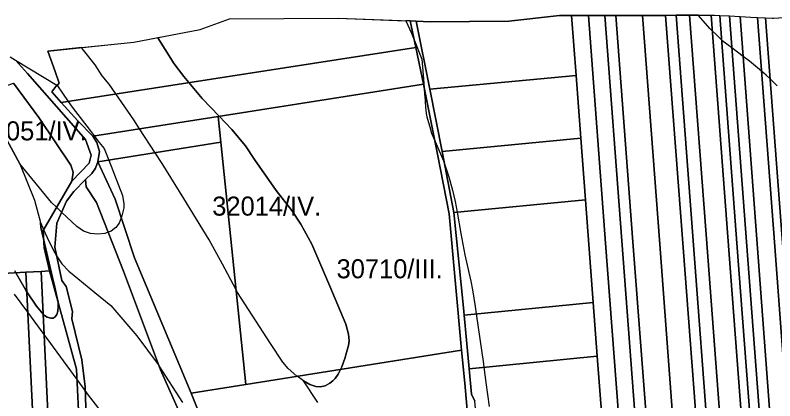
# Model space of a CAD drawing. Extents: x -521939 to -516426, y -1197857 to -1189551.
# Drawn here: x -519736 to -519138, y -1190305 to -1190001 of the extents above; entities that cross this region are included whole.
import ezdxf

# ---------------------------------------------------------------- set-up
doc = ezdxf.new("R2010")
doc.units = 0
for name, color, linetype in [('95560013', 7, 'Continuous'), ('95630013', 7, 'Continuous'), ('95640013', 7, 'Continuous'), ('95660013', 7, 'Continuous')]:
    doc.layers.add(name, color=color, linetype=linetype)

msp = doc.modelspace()

# ---------------------------------------------------------------- linework, layer by layer
at = {"layer": '95560013'}
for points in [[(-519481.8, -1190003.43), (-519425.02, -1190005.62), (-519420.54, -1190026.44), (-519524.15, -1190042.53), (-519700.01, -1190069.84), (-519707.58, -1190061.41), (-519703.4, -1190056.13), (-519701.77, -1190054.51), (-519704.94, -1190045.39), (-519710.52, -1190029.36), (-519655.77, -1190023.65), (-519642.78, -1190022.29), (-519590.6, -1190012.36), (-519567.31, -1190003.84)], [(-519347.33, -1190005.8), (-519307.47, -1190001.42), (-519297.85, -1190001.39), (-519294.3, -1190048.49), (-519409.64, -1190059.44), (-519420.4, -1190005.8), (-519409.39, -1190006.22)], [(-519286.91, -1190146.52), (-519290.57, -1190097.95), (-519294.3, -1190048.49), (-519297.85, -1190001.39), (-519284.59, -1190001.35), (-519271.04, -1190180.87), (-519257.49, -1190360.49), (-519243.94, -1190540.06), (-519241.8, -1190568.42), (-519254.99, -1190569.86), (-519260.41, -1190497.97), (-519273.79, -1190320.5), (-519277.61, -1190269.89), (-519280.81, -1190227.48)], [(-519271.58, -1190001.31), (-519258.19, -1190178.89), (-519244.8, -1190356.47), (-519231.41, -1190534.05), (-519228.93, -1190566.94), (-519241.8, -1190568.42), (-519243.94, -1190540.06), (-519257.49, -1190360.49), (-519271.04, -1190180.87), (-519284.59, -1190001.35)], [(-519263.01, -1190001.29), (-519249.51, -1190179.72), (-519236.01, -1190357.93), (-519222.51, -1190536.25), (-519220.26, -1190565.97), (-519228.93, -1190566.94), (-519231.41, -1190534.05), (-519244.8, -1190356.47), (-519258.19, -1190178.89), (-519271.58, -1190001.31)], [(-519241.98, -1190001.22), (-519228.37, -1190181.49), (-519214.76, -1190361.76), (-519201.15, -1190542.03), (-519199.52, -1190563.62), (-519220.26, -1190565.97), (-519222.51, -1190536.25), (-519236.01, -1190357.93), (-519249.51, -1190179.72), (-519263.01, -1190001.29)], [(-519223.76, -1190001.17), (-519209.94, -1190184.24), (-519196.08, -1190367.84), (-519181.45, -1190561.64), (-519199.52, -1190563.62), (-519201.15, -1190542.03), (-519214.76, -1190361.76), (-519228.37, -1190181.49), (-519241.98, -1190001.22)], [(-519188.32, -1190360.35), (-519174.76, -1190540.02), (-519173.2, -1190560.69), (-519181.45, -1190561.64), (-519196.08, -1190367.84), (-519209.94, -1190184.24), (-519223.76, -1190001.17), (-519215.43, -1190001.14), (-519203.35, -1190161.2)], [(-519204.78, -1190001.11), (-519190.45, -1190191.14), (-519177, -1190369.5), (-519162.67, -1190559.53), (-519173.2, -1190560.69), (-519174.76, -1190540.02), (-519188.32, -1190360.35), (-519203.35, -1190161.2), (-519215.43, -1190001.14)], [(-519145.9, -1190557.64), (-519162.67, -1190559.53), (-519177, -1190369.5), (-519190.45, -1190191.14), (-519204.78, -1190001.11), (-519187.9, -1190001.06), (-519174.72, -1190175.72), (-519161.62, -1190349.32), (-519148.48, -1190523.45)], [(-519139.11, -1190556.88), (-519145.9, -1190557.64), (-519148.48, -1190523.45), (-519161.62, -1190349.32), (-519174.72, -1190175.72), (-519187.9, -1190001.06), (-519185.31, -1190001.05), (-519181.03, -1190001.27), (-519167.49, -1190180.73), (-519153.91, -1190360.72)], [(-519173.46, -1190001.68), (-519158.96, -1190193.53), (-519146.06, -1190364.21), (-519131.56, -1190556.06), (-519139.11, -1190556.88), (-519153.91, -1190360.72), (-519167.49, -1190180.73), (-519181.03, -1190001.27)], [(-519123.38, -1190555.13), (-519131.56, -1190556.06), (-519146.06, -1190364.21), (-519158.96, -1190193.53), (-519173.46, -1190001.68), (-519165.08, -1190002.12), (-519151.32, -1190184.6), (-519137.79, -1190364.03)], [(-519151.35, -1190002.84), (-519137.72, -1190183.43), (-519123.85, -1190367.2), (-519109.78, -1190553.62), (-519123.38, -1190555.13), (-519137.79, -1190364.03), (-519151.32, -1190184.6), (-519165.08, -1190002.12), (-519156.46, -1190002.57)], [(-519103.47, -1190552.85), (-519109.78, -1190553.62), (-519123.85, -1190367.2), (-519137.72, -1190183.43), (-519151.35, -1190002.84), (-519144.96, -1190003.18)], [(-519103.47, -1190552.85), (-519144.96, -1190003.18), (-519139.71, -1190003.46), (-519138.66, -1190003.51), (-519126.22, -1190002.51), (-519084.87, -1190550.8)], [(-519420.54, -1190026.44), (-519414.58, -1190055.36), (-519576.32, -1190080.83), (-519675.13, -1190096.39), (-519686.92, -1190084.42), (-519700.01, -1190069.84), (-519524.15, -1190042.53)], [(-519409.64, -1190059.44), (-519294.3, -1190048.49), (-519290.57, -1190097.95), (-519399.76, -1190108.5)], [(-519737.67, -1190054.66), (-519717.63, -1190081.69), (-519692.57, -1190119.33), (-519690.61, -1190124.71), (-519691.71, -1190131.91), (-519714.39, -1190170.65), (-519713.62, -1190184.5), (-519709.23, -1190202.58), (-519715.93, -1190202.95), (-519727.94, -1190203.65), (-519755.55, -1190205.15), (-519762.5, -1190063.2)], [(-519554.65, -1190292.08), (-519574.25, -1190101.1), (-519576.32, -1190080.83), (-519414.58, -1190055.36), (-519403.44, -1190110.7), (-519394.35, -1190157.59), (-519384.52, -1190265.07)], [(-519574.25, -1190101.1), (-519671.12, -1190116.75), (-519669.83, -1190108.42), (-519672.04, -1190101.52), (-519675.13, -1190096.39), (-519576.32, -1190080.83)], [(-519286.91, -1190146.52), (-519390.55, -1190156.64), (-519399.76, -1190108.5), (-519290.57, -1190097.95)], [(-519280.81, -1190227.48), (-519382.51, -1190237.48), (-519383.05, -1190231.66), (-519390.55, -1190156.64), (-519286.91, -1190146.52)], [(-519727.94, -1190203.65), (-519719.31, -1190382.05), (-519710.68, -1190560.45), (-519708.85, -1190598.28), (-519736.61, -1190599.63), (-519738.41, -1190562.14), (-519747.01, -1190383.02), (-519755.55, -1190205.15)], [(-519708.85, -1190598.28), (-519710.68, -1190560.45), (-519719.31, -1190382.05), (-519727.94, -1190203.65), (-519715.93, -1190202.95), (-519707.58, -1190380.93), (-519705.04, -1190435.07), (-519704.15, -1190453.75), (-519697.37, -1190597.74)], [(-519685.58, -1190328.88), (-519686.63, -1190434.32), (-519705.04, -1190435.07), (-519707.58, -1190380.93), (-519715.93, -1190202.95), (-519709.23, -1190202.58), (-519687.95, -1190280.17)], [(-519382.51, -1190237.48), (-519280.81, -1190227.48), (-519277.61, -1190269.89), (-519378.52, -1190279.71)], [(-519552.15, -1190418.05), (-519575.87, -1190352.44), (-519580.3, -1190341.74), (-519589.71, -1190318.55), (-519597.55, -1190298.89), (-519554.65, -1190292.08), (-519384.52, -1190265.07), (-519381.99, -1190291.12), (-519379.73, -1190315.25), (-519378.72, -1190326.34), (-519371.85, -1190389.63), (-519359.02, -1190533.89), (-519508.5, -1190542.63)], [(-519378.52, -1190279.71), (-519277.61, -1190269.89), (-519273.79, -1190320.5), (-519373.77, -1190331.22), (-519372.25, -1190325.33), (-519374.13, -1190305.25), (-519376.64, -1190299.8)]]:
    msp.add_lwpolyline(points, close=True, dxfattribs=at)
at = {"layer": '95630013'}
for points in [[(-519740.21, -1190033.91), (-519736.08, -1190036.41), (-519726.6, -1190046.96), (-519680.84, -1190099.12), (-519676.51, -1190111.34), (-519678.13, -1190117.74), (-519691.71, -1190131.91), (-519690.61, -1190124.71), (-519692.57, -1190119.33), (-519717.63, -1190081.69), (-519737.67, -1190054.66)], [(-519605.33, -1190317.74), (-519621.92, -1190280.63), (-519650.97, -1190202.84), (-519672.17, -1190148.75), (-519680.32, -1190136.31), (-519680.93, -1190130.62), (-519676.05, -1190125.81), (-519673.07, -1190121.57), (-519671.12, -1190116.75), (-519657.67, -1190146.19), (-519642.29, -1190192.29), (-519597.55, -1190298.89), (-519589.71, -1190318.55)]]:
    msp.add_lwpolyline(points, dxfattribs=at)
at = {"layer": '95640013'}
for points in [[(-519379.73, -1190315.25), (-519381.99, -1190291.12), (-519384.52, -1190265.07), (-519394.35, -1190157.59), (-519403.44, -1190110.7), (-519414.58, -1190055.36), (-519420.54, -1190026.44), (-519425.02, -1190005.62), (-519420.4, -1190005.8), (-519409.64, -1190059.44), (-519399.76, -1190108.5), (-519390.55, -1190156.64), (-519383.05, -1190231.66), (-519382.51, -1190237.48), (-519378.52, -1190279.71), (-519376.64, -1190299.8), (-519374.13, -1190305.25)], [(-519685.58, -1190328.88), (-519687.95, -1190280.17), (-519709.23, -1190202.58), (-519713.62, -1190184.5), (-519714.39, -1190170.65), (-519691.71, -1190131.91), (-519678.13, -1190117.74), (-519676.51, -1190111.34), (-519680.84, -1190099.12), (-519726.6, -1190046.96), (-519736.08, -1190036.41), (-519703.4, -1190056.13), (-519707.58, -1190061.41), (-519700.01, -1190069.84), (-519686.92, -1190084.42), (-519675.13, -1190096.39), (-519672.04, -1190101.52), (-519669.83, -1190108.42), (-519671.12, -1190116.75), (-519673.07, -1190121.57), (-519676.05, -1190125.81), (-519680.93, -1190130.62), (-519690, -1190140), (-519695.89, -1190147.52), (-519703.56, -1190164.98), (-519705.08, -1190183.98), (-519699.51, -1190210.06), (-519696.18, -1190214.95), (-519691.12, -1190234.48), (-519691.66, -1190240.37), (-519683.84, -1190272.83), (-519681.25, -1190294.06), (-519680.51, -1190318.33)]]:
    msp.add_lwpolyline(points, dxfattribs=at)
for points in [[(-519657.67, -1190146.19), (-519671.12, -1190116.75), (-519574.25, -1190101.1), (-519554.65, -1190292.08), (-519597.55, -1190298.89), (-519642.29, -1190192.29)], [(-519605.33, -1190317.74), (-519680.51, -1190318.33), (-519681.25, -1190294.06), (-519683.84, -1190272.83), (-519691.66, -1190240.37), (-519691.12, -1190234.48), (-519696.18, -1190214.95), (-519699.51, -1190210.06), (-519705.08, -1190183.98), (-519703.56, -1190164.98), (-519695.89, -1190147.52), (-519690, -1190140), (-519680.93, -1190130.62), (-519680.32, -1190136.31), (-519672.17, -1190148.75), (-519650.97, -1190202.84), (-519621.92, -1190280.63)]]:
    msp.add_lwpolyline(points, close=True, dxfattribs=at)
at = {"layer": '95660013'}
for points in [[(-519497.69, -1190306.4), (-519509.17, -1190289.32), (-519504.06, -1190292.22), (-519499.31, -1190293.73), (-519495.95, -1190293.96), (-519492.13, -1190293.15), (-519488.42, -1190291.18), (-519485.87, -1190289.21), (-519484.13, -1190287.47), (-519481.81, -1190284.11), (-519479.95, -1190280.22), (-519479.03, -1190278.31), (-519476.48, -1190271.59), (-519475.15, -1190267.01), (-519473.7, -1190261.39), (-519473.46, -1190259.5), (-519473.23, -1190257.68), (-519473.47, -1190255.05), (-519473.7, -1190252.58), (-519475.78, -1190244.7), (-519488.3, -1190214.56), (-519502.67, -1190181.41), (-519511.25, -1190165.65), (-519518.21, -1190154.98), (-519530.72, -1190139.22), (-519547.76, -1190114.76), (-519554.95, -1190103.98), (-519565.5, -1190091.23), (-519575.57, -1190080.71), (-519589.03, -1190066.66), (-519599.44, -1190054.23), (-519603.4, -1190049.5), (-519610.93, -1190039.3), (-519618.12, -1190028.06), (-519623.82, -1190018.98), (-519623.66, -1190018.65), (-519590.6, -1190012.36), (-519567.31, -1190003.84), (-519481.8, -1190003.43)], [(-519481.8, -1190003.43), (-519428.42, -1190005.49), (-519423.87, -1190015.24), (-519421.85, -1190020.37), (-519415.8, -1190035.69), (-519414.69, -1190048), (-519414.01, -1190058.2), (-519413.63, -1190063.86), (-519413.58, -1190064.61), (-519413.24, -1190069.15), (-519412.91, -1190073.69), (-519412.74, -1190075.74), (-519412.52, -1190078.42), (-519411.89, -1190081.13), (-519410.7, -1190085.52), (-519409.63, -1190089.01), (-519408.11, -1190093.97), (-519405.47, -1190100.54), (-519398.08, -1190117.68), (-519397.91, -1190118.19), (-519394.44, -1190128.36), (-519391.74, -1190138.92), (-519389.63, -1190147.84), (-519388.08, -1190156.4), (-519385.05, -1190173.2), (-519381.88, -1190189.86), (-519378.71, -1190203.83), (-519377.3, -1190210.72), (-519375.9, -1190217.56), (-519373.93, -1190230.79), (-519373.07, -1190236.55), (-519367.21, -1190275.9), (-519366.89, -1190278.58), (-519365.45, -1190290.57), (-519362.75, -1190309.47)], [(-519135.7, -1190056.65), (-519141.33, -1190051.27), (-519144.51, -1190048.23), (-519148.15, -1190045.23), (-519157.72, -1190037.33), (-519162.71, -1190033.52), (-519171.56, -1190026.76), (-519179.28, -1190020.87), (-519179.57, -1190020.58), (-519184.15, -1190016.12), (-519186.97, -1190013.38), (-519187.48, -1190012.88), (-519188.79, -1190011.6), (-519197.76, -1190001.3), (-519197.88, -1190001.09), (-519204.78, -1190001.11), (-519215.43, -1190001.14), (-519223.76, -1190001.17), (-519241.98, -1190001.22), (-519263.01, -1190001.29), (-519271.58, -1190001.31), (-519284.59, -1190001.35), (-519297.85, -1190001.39), (-519307.47, -1190001.42), (-519347.33, -1190005.8), (-519409.39, -1190006.22), (-519420.4, -1190005.8), (-519425.02, -1190005.62), (-519428.42, -1190005.49), (-519423.87, -1190015.24), (-519421.85, -1190020.37), (-519415.8, -1190035.69), (-519414.69, -1190048), (-519414.01, -1190058.2), (-519413.63, -1190063.86), (-519413.58, -1190064.61), (-519413.24, -1190069.15), (-519412.91, -1190073.69), (-519412.74, -1190075.74), (-519412.52, -1190078.42), (-519411.89, -1190081.13), (-519410.7, -1190085.52), (-519409.63, -1190089.01), (-519408.11, -1190093.97), (-519405.47, -1190100.54), (-519398.08, -1190117.68), (-519397.91, -1190118.19), (-519394.44, -1190128.36), (-519391.74, -1190138.92), (-519389.63, -1190147.84), (-519388.08, -1190156.4), (-519385.05, -1190173.2), (-519381.88, -1190189.86), (-519378.71, -1190203.83), (-519377.3, -1190210.72), (-519375.9, -1190217.56), (-519373.93, -1190230.79), (-519373.07, -1190236.55), (-519367.21, -1190275.9), (-519366.89, -1190278.58), (-519365.45, -1190290.57), (-519362.75, -1190309.47)], [(-519135.7, -1190056.65), (-519141.33, -1190051.27), (-519144.51, -1190048.23), (-519148.15, -1190045.23), (-519157.72, -1190037.33), (-519162.71, -1190033.52), (-519171.56, -1190026.76), (-519179.28, -1190020.87), (-519179.57, -1190020.58), (-519184.15, -1190016.12), (-519186.97, -1190013.38), (-519187.48, -1190012.88), (-519188.79, -1190011.6), (-519197.76, -1190001.3), (-519197.88, -1190001.09), (-519187.9, -1190001.06), (-519185.31, -1190001.05), (-519181.03, -1190001.27), (-519173.46, -1190001.68), (-519165.08, -1190002.12), (-519156.46, -1190002.57), (-519151.35, -1190002.84), (-519144.96, -1190003.18), (-519139.71, -1190003.46), (-519138.66, -1190003.51), (-519126.22, -1190002.51)], [(-519642.78, -1190022.29), (-519623.66, -1190018.65), (-519623.82, -1190018.98), (-519618.12, -1190028.06), (-519610.93, -1190039.3), (-519603.4, -1190049.5), (-519599.44, -1190054.23), (-519589.03, -1190066.66), (-519575.57, -1190080.71), (-519565.5, -1190091.23), (-519554.95, -1190103.98), (-519547.76, -1190114.76), (-519530.72, -1190139.22), (-519518.21, -1190154.98), (-519511.25, -1190165.65), (-519502.67, -1190181.41), (-519488.3, -1190214.56), (-519475.78, -1190244.7), (-519473.7, -1190252.58), (-519473.47, -1190255.05), (-519473.23, -1190257.68), (-519473.46, -1190259.5), (-519473.7, -1190261.39), (-519475.15, -1190267.01), (-519476.48, -1190271.59), (-519479.03, -1190278.31), (-519479.95, -1190280.22), (-519481.81, -1190284.11), (-519484.13, -1190287.47), (-519485.87, -1190289.21), (-519488.42, -1190291.18), (-519492.13, -1190293.15), (-519495.95, -1190293.96), (-519499.31, -1190293.73), (-519504.06, -1190292.22), (-519509.17, -1190289.32), (-519514.2, -1190285.66), (-519514.26, -1190285.61), (-519521.1, -1190279.59), (-519525.39, -1190274.49), (-519535.25, -1190259.77), (-519561.21, -1190219.55), (-519562.31, -1190217.47), (-519572.92, -1190197.35), (-519583.58, -1190178.11), (-519603.52, -1190145.65), (-519620.44, -1190117.83), (-519625.93, -1190109.45), (-519638.3, -1190090.59), (-519642.93, -1190083.52), (-519656.9, -1190063.15), (-519662.17, -1190055.47), (-519667.67, -1190048.92), (-519673.43, -1190040.19), (-519683.44, -1190027.33), (-519683.69, -1190027.01), (-519683.94, -1190026.69), (-519684.06, -1190026.6), (-519655.77, -1190023.65), (-519642.78, -1190022.29)], [(-519497.69, -1190306.4), (-519509.17, -1190289.32), (-519514.2, -1190285.66), (-519514.26, -1190285.61), (-519521.1, -1190279.59), (-519525.39, -1190274.49), (-519535.25, -1190259.77), (-519561.21, -1190219.55), (-519562.31, -1190217.47), (-519572.92, -1190197.35), (-519583.58, -1190178.11), (-519603.52, -1190145.65), (-519620.44, -1190117.83), (-519625.93, -1190109.45), (-519638.3, -1190090.59), (-519642.93, -1190083.52), (-519656.9, -1190063.15), (-519662.17, -1190055.47), (-519667.67, -1190048.92), (-519673.43, -1190040.19), (-519683.44, -1190027.33), (-519683.69, -1190027.01), (-519683.94, -1190026.69), (-519684.06, -1190026.6), (-519710.52, -1190029.36), (-519704.94, -1190045.39), (-519701.77, -1190054.51), (-519701.8, -1190054.54), (-519702.22, -1190054.96), (-519703.12, -1190056.11), (-519703.33, -1190056.39), (-519703.28, -1190056.46), (-519703.03, -1190056.81), (-519694.47, -1190068.98), (-519691.32, -1190073.46), (-519677.32, -1190091.89), (-519674.05, -1190096.22), (-519670.09, -1190101.46), (-519666.24, -1190106.24), (-519662.64, -1190115.38), (-519651.66, -1190143.21), (-519650.73, -1190149.74), (-519650.73, -1190153.01), (-519652.59, -1190160.24), (-519652.8, -1190160.77), (-519654.46, -1190164.91), (-519657.03, -1190168.41), (-519660.76, -1190171.21), (-519663.03, -1190172.07), (-519665.66, -1190173.07), (-519671.26, -1190173.54), (-519677.09, -1190173.07), (-519682.45, -1190171.21), (-519687.82, -1190167.71), (-519699.72, -1190156.23), (-519703.7, -1190152.39), (-519707.65, -1190148.58), (-519732.61, -1190118.14), (-519721.06, -1190146.83), (-519716.4, -1190164.44), (-519713.95, -1190169.9), (-519709.75, -1190179.25), (-519705.08, -1190188.47), (-519703.66, -1190190.63), (-519699.48, -1190196.98), (-519694, -1190202.93), (-519687, -1190208.65), (-519673.47, -1190219.5), (-519661.05, -1190229.82), (-519640.52, -1190253.85), (-519623.73, -1190276.47), (-519623.12, -1190277.43), (-519604.6, -1190306.33)], [(-519740.21, -1190033.91), (-519736.08, -1190036.41), (-519703.4, -1190056.13), (-519701.8, -1190054.54), (-519702.22, -1190054.96), (-519703.12, -1190056.11), (-519703.33, -1190056.39), (-519703.28, -1190056.46), (-519703.03, -1190056.81), (-519694.47, -1190068.98), (-519691.32, -1190073.46), (-519677.32, -1190091.89), (-519674.05, -1190096.22), (-519670.09, -1190101.46), (-519666.24, -1190106.24), (-519662.64, -1190115.38), (-519651.66, -1190143.21), (-519650.73, -1190149.74), (-519650.73, -1190153.01), (-519652.59, -1190160.24), (-519652.8, -1190160.77), (-519654.46, -1190164.91), (-519657.03, -1190168.41), (-519660.76, -1190171.21), (-519663.03, -1190172.07), (-519665.66, -1190173.07), (-519671.26, -1190173.54), (-519677.09, -1190173.07), (-519682.45, -1190171.21), (-519687.82, -1190167.71), (-519699.72, -1190156.23), (-519703.7, -1190152.39), (-519707.65, -1190148.58), (-519732.61, -1190118.14), (-519747.89, -1190090.02)], [(-519747.89, -1190090.02), (-519732.61, -1190118.14), (-519721.06, -1190146.83), (-519716.4, -1190164.44), (-519716.05, -1190168.52), (-519714.01, -1190177.44), (-519707.07, -1190207.83), (-519705.23, -1190215.42), (-519702.63, -1190226.14), (-519702.6, -1190226.76), (-519702.4, -1190230.69), (-519702.63, -1190234.31), (-519703.45, -1190236.99), (-519704.85, -1190238.86), (-519706.37, -1190239.79), (-519708.23, -1190239.91), (-519711.15, -1190239.09), (-519713.95, -1190237.22), (-519714.35, -1190236.75), (-519719.66, -1190230.46), (-519727.19, -1190219.06), (-519728.06, -1190217.75), (-519735.84, -1190204.08), (-519736.69, -1190202.58)], [(-519736.69, -1190202.58), (-519735.84, -1190204.08), (-519728.06, -1190217.75), (-519727.19, -1190219.06), (-519719.66, -1190230.46), (-519714.35, -1190236.75), (-519713.95, -1190237.22), (-519711.15, -1190239.09), (-519708.23, -1190239.91), (-519706.37, -1190239.79), (-519704.85, -1190238.86), (-519703.45, -1190236.99), (-519702.63, -1190234.31), (-519702.4, -1190230.69), (-519702.6, -1190226.76), (-519702.63, -1190226.14), (-519705.23, -1190215.42), (-519707.07, -1190207.83), (-519714.01, -1190177.44), (-519716.05, -1190168.52), (-519716.4, -1190164.44), (-519713.95, -1190169.9), (-519709.75, -1190179.25), (-519705.08, -1190188.47), (-519703.66, -1190190.63), (-519699.48, -1190196.98), (-519694, -1190202.93), (-519687, -1190208.65), (-519673.47, -1190219.5), (-519661.05, -1190229.82), (-519640.52, -1190253.85), (-519623.73, -1190276.47), (-519623.12, -1190277.43), (-519604.6, -1190306.33)], [(-519664.97, -1190318.21), (-519678.55, -1190300.5), (-519681.16, -1190296.94), (-519687.56, -1190288.21), (-519711.21, -1190255.95), (-519713.6, -1190252.69), (-519726.41, -1190235.21), (-519736.87, -1190220.95)], [(-519664.97, -1190318.21), (-519678.55, -1190300.5), (-519681.16, -1190296.94), (-519687.56, -1190288.21), (-519711.21, -1190255.95), (-519713.6, -1190252.69), (-519726.41, -1190235.21), (-519736.87, -1190220.95)]]:
    msp.add_lwpolyline(points, dxfattribs=at)

# ---------------------------------------------------------------- texts
for s, rotation, p in [('32051/IV.', 360, (-519765.91, -1190099.72)), ('32014/IV.', 0, (-519581.03, -1190159.03)), ('30710/III.', 360, (-519483.04, -1190208.43))]:
    msp.add_text(s, height=15, rotation=rotation, dxfattribs=at).set_placement(p)

doc.saveas('drawing.dxf')
